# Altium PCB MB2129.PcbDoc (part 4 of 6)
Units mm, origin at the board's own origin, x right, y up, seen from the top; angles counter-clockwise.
Board outline 70 x 133.34 mm, 6 copper layers (Top Layer, Signal Layer 1, Signal Layer 2, Signal Layer 3, Signal Layer 4, Bottom Layer), stack 1.57 mm thick; 377 components, 289 nets, 1482 pads, 1373 vias.
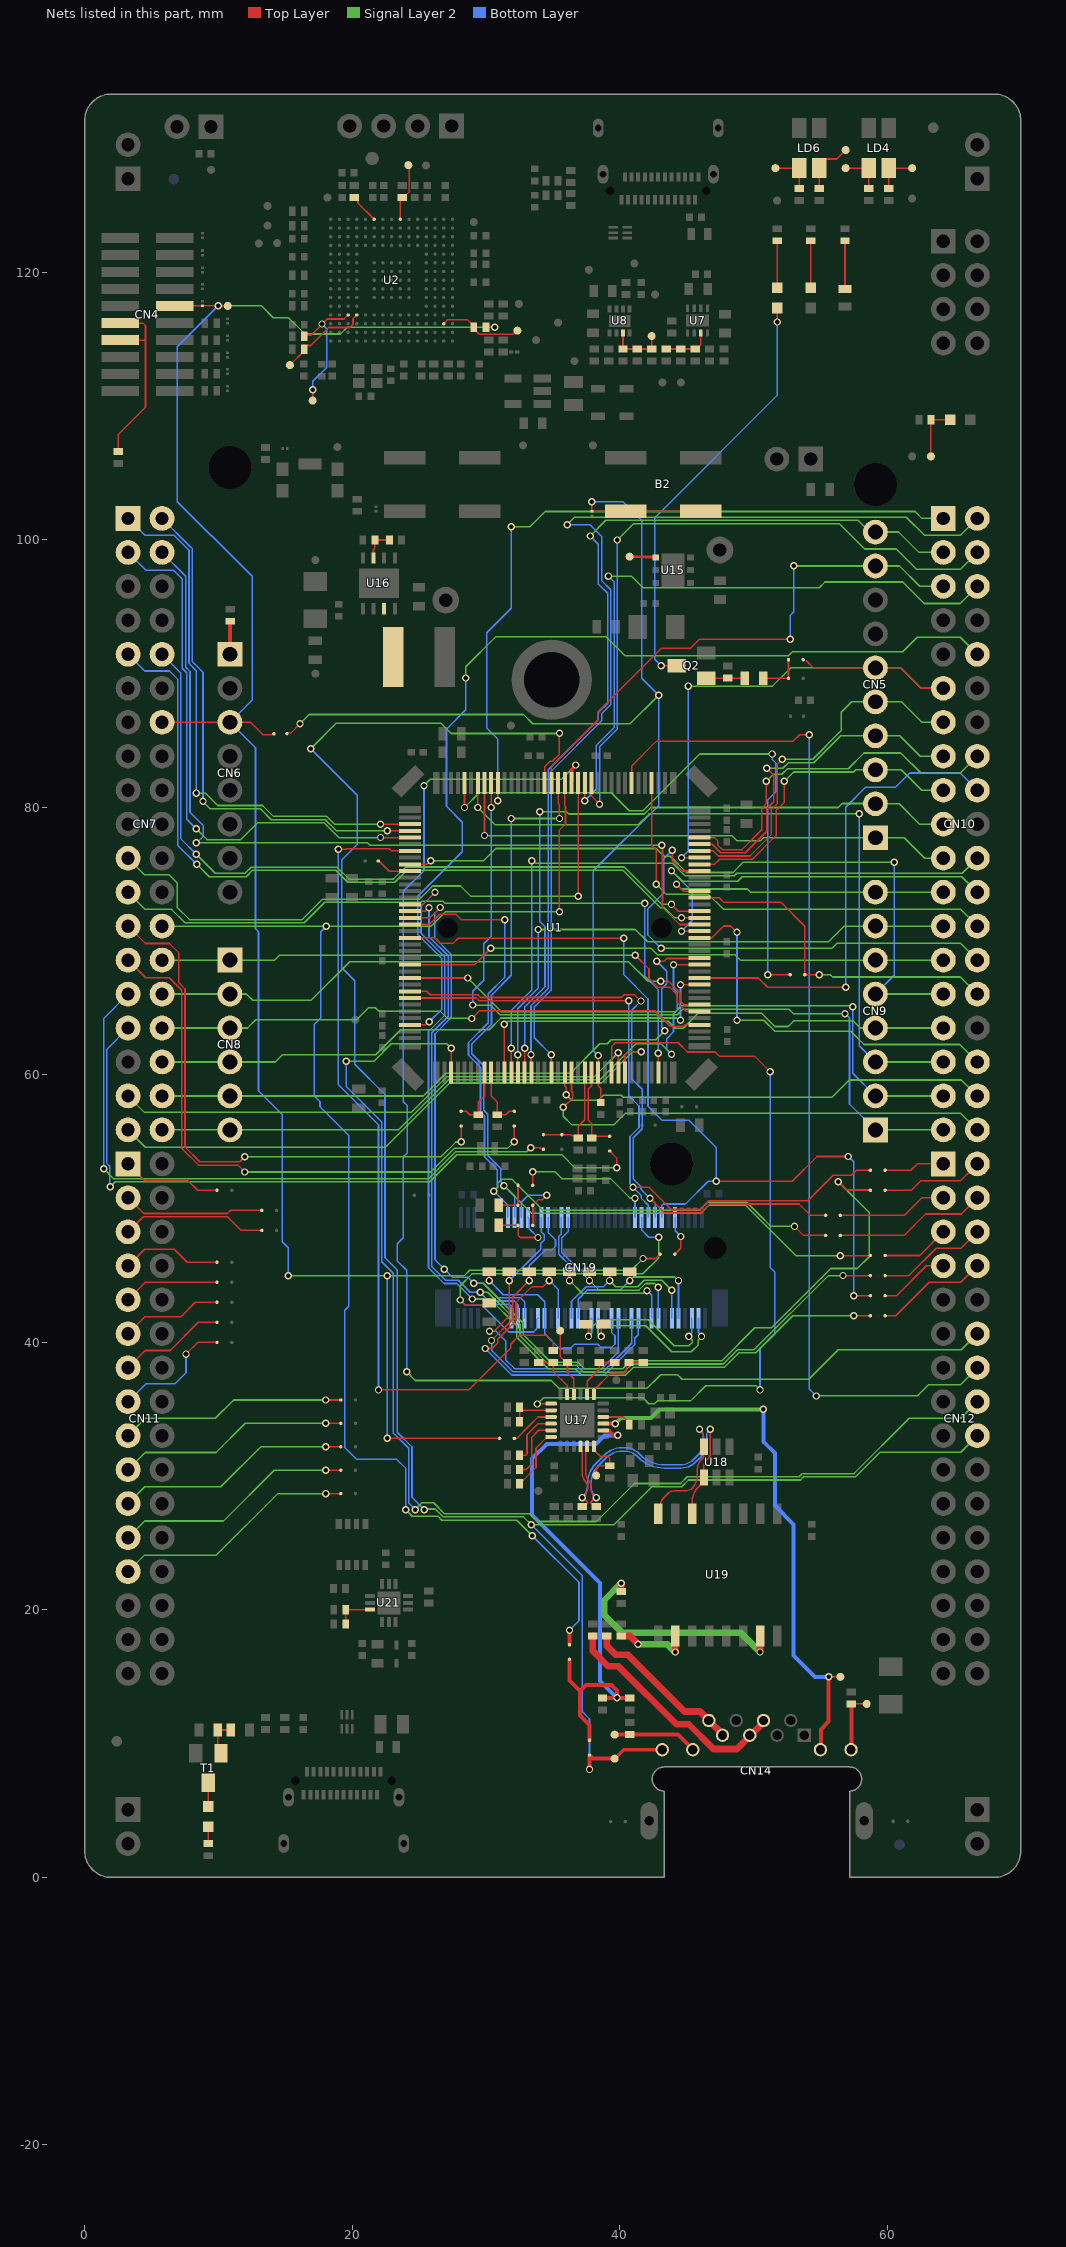
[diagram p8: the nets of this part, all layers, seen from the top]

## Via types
v1: diameter 0.55, hole 0.35, Top Layer to Bottom Layer, tented both sides, 1373 vias

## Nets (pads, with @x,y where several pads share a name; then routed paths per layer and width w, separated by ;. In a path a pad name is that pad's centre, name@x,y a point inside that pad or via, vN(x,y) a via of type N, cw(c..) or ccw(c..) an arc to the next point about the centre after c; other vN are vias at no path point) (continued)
NetCN4_11: CN4.11 CN4.13 R50.2 | length 14.1
  Top Layer w0.12: R50.2@2.5,106.625 2.5,107.871 4.55,109.921 4.55,114.929 ; CN4.13@2.665,114.945 4.534,114.945 4.55,114.929 ; CN4.11@2.665,116.215 4.36,116.215 4.55,116.025 4.55,114.929
NetCN6_1: CN6.1 R59.1 | length 2.5
  Top Layer w0.12: CN6.1@10.866,91.45 CN6.1@10.875,91.459
  Top Layer w0.3: CN6.1@10.875,91.459 R59.1@10.875,93.925
NetCN11_1: CN11.1 SB7.2 | length 7.5
  Top Layer w0.12: CN11.1@3.246,53.35 4.496,52.1 7.725,52.1 8.45,51.375 SB7.2@9.9,51.375
NetCN11_3: CN11.3 SB15.2 | length 10.6
  Top Layer w0.12: CN11.3@3.246,50.81 4.416,49.64 10.683,49.64 10.918,49.875 SB15.2@13.25,49.875
NetCN11_5: CN11.5 SB16.2 | length 10.9
  Top Layer w0.12: CN11.5@3.246,48.27 4.376,49.4 10.675,49.4 11.7,48.375 SB16.2@13.25,48.375
NetCN11_7: CN11.7 SB17.2 | length 7.6
  Top Layer w0.12: CN11.7@3.246,45.73 4.491,46.975 6.7,46.975 7.675,46 SB17.2@9.9,46
NetCN11_9: CN11.9 SB18.2 | length 7.2
  Top Layer w0.12: CN11.9@3.246,43.19 4.556,44.5 SB18.2@9.9,44.5
NetCN11_11: CN11.11 SB20.2 | length 7.6
  Top Layer w0.12: CN11.11@3.246,40.65 4.521,41.925 7.2,41.925 8.275,43 SB20.2@9.9,43
NetCN11_13: CN11.13 SB21.2 | length 8.1
  Top Layer w0.12: CN11.13@3.246,38.11 4.536,39.4 6.4,39.4 8.5,41.5 SB21.2@9.9,41.5
NetCN11_15: CN11.15 SB22.2 | length 9.3
  Top Layer w0.12: v1(7.579,39.13) 8.449,40 SB22.2@9.9,40
  Bottom Layer w0.12: CN11.15@3.246,35.57 4.576,36.9 6.734,36.9 7.579,37.744 v1(7.579,39.13)
NetCN11_17: CN11.17 SB23.2 | length 17
  Top Layer w0.12: v1(18.025,35.7) SB23.2@19.15,35.7
  Signal Layer 2 w0.12: CN11.17@3.246,33.03 4.541,34.325 9.775,34.325 11.15,35.7 v1(18.025,35.7)
NetCN11_19: CN11.19 SB24.2 | length 17.3
  Top Layer w0.12: v1(18.025,33.95) SB24.2@19.15,33.95
  Signal Layer 2 w0.12: CN11.19@3.246,30.49 4.531,31.775 9.825,31.775 12,33.95 v1(18.025,33.95)
NetCN11_21: CN11.21 SB28.2 | length 17.7
  Top Layer w0.12: v1(18.025,32.2) SB28.2@19.15,32.2
  Signal Layer 2 w0.12: CN11.21@3.246,27.95 4.496,29.2 10.186,29.2 13.186,32.2 v1(18.025,32.2)
NetCN11_23: CN11.23 SB26.2 | length 18
  Top Layer w0.12: v1(18.025,30.45) SB26.2@19.15,30.45
  Signal Layer 2 w0.12: CN11.23@3.246,25.41 4.486,26.65 10.375,26.65 14.175,30.45 v1(18.025,30.45)
NetCN11_25: CN11.25 SB27.2 | length 18.3
  Top Layer w0.12: v1(18.025,28.7) SB27.2@19.15,28.7
  Signal Layer 2 w0.12: CN11.25@3.246,22.87 4.476,24.1 9.85,24.1 14.45,28.7 v1(18.025,28.7)
NetCN12_1: CN12.1 SB29.2 | length 4.6
  Top Layer w0.12: SB29.2@59.85,52.875 61.775,52.875 62.25,53.35 CN12.1@64.206,53.35
NetCN12_2: CN12.2 SB31.2 | length 7.7
  Top Layer w0.12: SB31.2@59.85,51.375 61.825,51.375 62.525,52.075 65.471,52.075 CN12.2@66.746,53.35
NetCN12_3: CN12.3 SB30.2 | length 8.3
  Top Layer w0.12: SB30.2@56.5,49.5 61.3,49.5 62.61,50.81 CN12.3@64.206,50.81
  Signal Layer 2 w0.12: CN12.3@64.198,50.818 CN12.3@64.206,50.81
NetCN12_4: CN12.4 SB34.2 | length 11.4
  Top Layer w0.12: SB34.2@56.5,48 61.275,48 62.875,49.6 65.536,49.6 CN12.4@66.746,50.81
NetCN12_5: CN12.5 SB36.2 | length 5.1
  Top Layer w0.12: SB36.2@59.85,46.5 62.436,46.5 CN12.5@64.206,48.27
  Signal Layer 2 w0.12: CN12.5@64.203,48.273 CN12.5@64.206,48.27
NetCN12_6: CN12.6 SB33.2 | length 8.3
  Top Layer w0.12: SB33.2@59.85,45 61.625,45 63.675,47.05 65.526,47.05 CN12.6@66.746,48.27
NetCN12_7: CN12.7 SB37.2 | length 5.3
  Top Layer w0.12: SB37.2@59.85,43.5 60.697,43.5 62.927,45.73 CN12.7@64.206,45.73
  Signal Layer 2 w0.12: CN12.7@64.196,45.74 CN12.7@64.206,45.73
NetCN12_8: CN12.8 SB32.2 | length 8.4
  Top Layer w0.12: SB32.2@59.85,42 60.65,42 63.15,44.5 65.516,44.5 CN12.8@66.746,45.73
NetCN14_4: CN14.4 CN14.5 R92.2 | length 17.9
  Top Layer w0.5: R92.2@37.997,18.054 37.997,16.929 39.147,15.779 39.922,15.779 44.247,11.454 45.172,11.454 47.022,9.604 48.769,9.604 49.765,10.6 50.785,11.62 CN14.4@50.785,11.7
NetCN14_7: CN14.7 CN14.8 R93.2 | length 12.3
  Top Layer w0.5: R93.2@39.047,18.054 39.047,17.304 39.697,16.654 40.597,16.654 44.847,12.404 46.001,12.404 46.705,11.7 47.725,10.68 CN14.7@47.725,10.6
NetCN14_9: CN14.9 R95.2 TP69.1 | length 4.6
  Top Layer w0.12: R95.2@57.325,12.975 TP69.1@58.475,12.975
  Top Layer w0.3: R95.2@57.325,12.975 57.335,12.965 CN14.9@57.335,9.52
NetCN14_10: CN14.10 TP65.1 U17.3 | length 41.6
  Top Layer w0.12: v1(55.625,15) TP65.1@56.5,15
  Top Layer w0.3: U17.3@38.775,33.925 v1(39.675,33.925) ; CN14.10@55.045,9.52 55.045,11.064 55.625,11.644 v1(55.625,15)
  Signal Layer 2 w0.3: v1(39.675,33.925) 40.115,34.365 42.359,34.365 42.994,35 v1(50.75,35)
  Bottom Layer w0.3: v1(50.75,35) 50.75,32.575 51.6,31.725 51.6,27.8 53,26.4 53,16.6 54.15,15.45 54.6,15 v1(55.625,15)
NetCN14_11: CN14.11 R102.2 TP72.1 | length 6.3
  Top Layer w0.3: TP72.1@39.625,10.675 R102.2@40.75,10.675 44.35,10.675 CN14.11@45.475,9.55
NetCN19_20: CN19.20 SB11.1 SB12.1 | length 6.1
  Top Layer w0.12: SB11.1@33.5,48.75 SB12.1@33.5,50.25 33.933,50.683 34.263,50.683 34.55,50.97 v1(34.55,51)
  Bottom Layer w0.12: CN19.20@32.65,49.35 32.65,50.475 33.175,51 v1(34.55,51)
NetCN19_22: CN19.22 R67.2 SB11.2 | length 5.6
  Top Layer w0.12: R67.2@30.95,48.75 SB11.2@32.4,48.75 32.425,48.725 32.425,48 32.575,47.85 v1(33.9,47.85)
  Bottom Layer w0.12: CN19.22@33.15,49.35 33.24,49.26 33.24,48.51 v1(33.9,47.85)
NetCN19_25: CN19.25 CN19.56 R107.2 | length 30.8
  Top Layer w0.12: v1(28.075,43.175) 28.475,42.775 30.075,42.775 R107.2@30.25,42.95
  Signal Layer 2 w0.12: v1(28.075,43.175) 28.075,44.239 28.961,45.125 40.925,45.125 40.93,45.13 41.735,45.13 42.925,46.32 v1(42.925,47.875)
  Bottom Layer w0.12: v1(28.075,43.175) 28.475,42.775 29.713,42.775 31.708,40.78 33.56,40.78 33.81,41.03 33.81,41.71 CN19.25@33.9,41.8 ; CN19.56@41.65,49.35 41.65,48.411 42.186,47.875 v1(42.925,47.875)
NetCN19_26: CN19.26 CN19.49 R63.2 | length 26.3
  Top Layer w0.12: v1(30.275,40.825) 30.314,40.864 30.639,40.864 31.75,41.975 v1(31.75,44.625) R63.2@31.75,45.3 31.61,45.3 R63.2@31.35,45.04
  Bottom Layer w0.12: v1(30.275,40.825) 30.775,40.825 31.496,40.104 31.496,38.683 32.134,38.045 38.656,38.045 39.9,39.289 CN19.49@39.9,41.8 ; v1(31.75,44.625) 34.1,46.975 34.1,47.407 34.355,47.662 34.355,48.046 34.15,48.251 CN19.26@34.15,49.35
NetCN19_27: CN19.27 CN19.47 R66.2 | length 15.9
  Top Layer w0.12: v1(30.25,44.625) R66.2@30.25,45.3
  Bottom Layer w0.12: v1(30.25,44.625) 31.3,43.575 33.875,43.575 34.4,43.05 CN19.27@34.4,41.8 34.4,40.65 35.504,39.546 36.31,39.546 36.619,39.855 38.372,39.855 38.607,39.62 39.388,39.62 39.655,39.887 39.655,40.492 39.4,40.747 CN19.47@39.4,41.8
NetCN19_28: CN19.28 CN19.53 R58.2 | length 27
  Top Layer w0.12: v1(30.425,40.15) 32.004,41.729 32.004,43.379 v1(33.25,44.625) R58.2@33.25,45.3
  Bottom Layer w0.12: v1(30.425,40.15) 30.425,39.414 32.034,37.805 38.755,37.805 40.9,39.95 CN19.53@40.9,41.8 ; v1(33.25,44.625) 33.25,45.733 34.437,46.92 34.938,46.92 35.205,47.187 35.205,47.688 34.65,48.243 CN19.28@34.65,49.35
NetCN19_31: CN19.31 CN19.55 R57.2 | length 26.7
  Top Layer w0.12: v1(29.95,39.55) 30.468,39.55 30.88,39.962 30.88,40.248 32.25,41.618 32.25,42.982 33.443,44.175 34.3,44.175 v1(34.75,44.625) R57.2@34.75,45.3
  Bottom Layer w0.12: v1(29.95,39.55) 31.935,37.565 38.854,37.565 41.14,39.851 41.14,40.315 41.4,40.575 CN19.55@41.4,41.8 ; v1(34.75,44.625) 35.4,43.975 CN19.31@35.4,41.8
NetCN19_32: CN19.32 CN19.59 R56.2 | length 14.3
  Top Layer w0.12: v1(36.25,44.625) R56.2@36.25,45.3
  Signal Layer 2 w0.12: v1(36.25,44.625) 37.2,43.675 41.765,43.675 41.965,43.875 v1(42.05,43.875)
  Bottom Layer w0.12: CN19.32@35.65,49.35 35.65,48.133 35.445,47.928 35.445,46.6 36.25,45.795 v1(36.25,44.625) ; v1(42.05,43.875) 42.4,43.525 CN19.59@42.4,41.8
NetCN19_34: CN19.34 CN19.61 R53.2 | length 14.6
  Top Layer w0.12: v1(37.75,44.625) R53.2@37.75,45.3
  Signal Layer 2 w0.12: v1(37.75,44.625) 38.46,43.915 41.447,43.915 41.942,44.41 42.641,44.41 42.9,44.151 v1(42.9,44.125)
  Bottom Layer w0.12: CN19.34@36.15,49.35 36.15,48.294 35.685,47.829 35.685,46.699 37.75,44.634 v1(37.75,44.625) ; CN19.61@42.9,41.8 v1(42.9,44.125)
NetCN19_35: CN19.35 CN19.65 R52.2 | length 12.9
  Top Layer w0.12: v1(39.25,44.625) R52.2@39.25,45.3
  Signal Layer 2 w0.12: v1(39.25,44.625) 39.72,44.155 41.347,44.155 41.842,44.65 43.15,44.65 v1(43.9,43.9)
  Bottom Layer w0.12: CN19.35@36.4,41.8 36.4,43.075 37.495,44.17 38.795,44.17 v1(39.25,44.625) ; CN19.65@43.9,41.8 v1(43.9,43.9)
NetCN19_37: CN19.37 CN19.67 R51.2 | length 13.2
  Top Layer w0.12: v1(40.75,44.625) R51.2@40.75,45.3
  Signal Layer 2 w0.12: v1(40.75,44.625) 40.764,44.625 41.029,44.89 44.121,44.89 44.386,44.625 v1(44.4,44.625)
  Bottom Layer w0.12: CN19.37@36.9,41.8 36.9,43.236 37.589,43.925 40.05,43.925 v1(40.75,44.625) ; CN19.67@44.4,41.8 v1(44.4,44.625)
NetCN19_41: CN19.41 CN19.71 R108.2 | length 13.8
  Top Layer w0.12: R108.2@37.475,41.35 37.675,41.15 v1(37.675,40.45)
  Signal Layer 2 w0.12: v1(37.675,40.45) 37.675,40.468 37.925,40.718 37.925,41.111 38.514,41.7 42.136,41.7 44.086,39.75 45.175,39.75 45.425,40 45.425,40.182 45.175,40.432 v1(45.175,40.45)
  Bottom Layer w0.12: v1(37.675,40.45) 37.675,40.509 37.9,40.734 CN19.41@37.9,41.8 ; v1(45.175,40.45) 45.175,40.509 45.4,40.734 CN19.71@45.4,41.8
NetCN19_43: CN19.43 CN19.73 R109.2 | length 13.8
  Top Layer w0.12: v1(38.625,40.45) 38.625,41.15 R109.2@38.825,41.35
  Signal Layer 2 w0.12: v1(38.625,40.45) 38.625,40.468 38.375,40.718 38.375,40.925 38.7,41.25 41.95,41.25 43.9,39.3 45.361,39.3 45.875,39.814 45.875,40.182 46.125,40.432 v1(46.125,40.45)
  Bottom Layer w0.12: CN19.43@38.4,41.8 38.4,40.734 38.625,40.509 v1(38.625,40.45) ; CN19.73@45.9,41.8 45.9,40.734 46.125,40.509 v1(46.125,40.45)
NetCN19_54: CN19.54 SB39.1 | length 10.9
  Top Layer w0.12: SB39.1@33.5,51.75 v1(33.5,52.75)
  Signal Layer 2 w0.12: v1(33.5,52.75) 35.19,52.75 35.715,52.225 39.35,52.225 40.773,50.802 41.123,50.802 v1(41.15,50.775)
  Bottom Layer w0.12: CN19.54@41.15,49.35 v1(41.15,50.775)
NetCN19_66: CN19.66 SB25.1 | length 3.1
  Top Layer w0.12: SB25.1@44.125,46.6 44.575,47.05 v1(44.575,47.925)
  Bottom Layer w0.12: CN19.66@44.15,49.35 44.15,48.35 v1(44.575,47.925)
NetL2_1: L2.1 U16.7
NetLD1_1: LD1.1 R17.1 | length 3.5
  Top Layer w0.12: LD1.1@51.775,118.85 R17.1@51.775,122.375
NetLD1_2: LD1.2 Q2.3 | length 31.9
  Top Layer w0.12: v1(43.1,90.6) Q2.3@44.277,90.6 ; v1(51.775,116.3) LD1.2@51.775,117.35
  Bottom Layer w0.12: v1(43.1,90.6) 42.625,91.075 42.625,101.65 51.775,110.8 v1(51.775,116.3)
NetLD2_1: LD2.1 R18.1 | length 3.5
  Top Layer w0.12: LD2.1@54.3,118.85 R18.1@54.3,122.375
NetLD3_1: LD3.1 R19.1 | length 3.5
  Top Layer w0.12: LD3.1@56.85,118.85 R19.1@56.85,122.375
NetLD4_1: LD4.1 R12.1 TP7.1 | length 3.3
  Top Layer w0.12: R12.1@60.125,126.275 LD4.1@60.125,127.8 TP7.1@61.875,127.8
NetLD4_2: LD4.2 R11.2 TP6.1 | length 3.2
  Top Layer w0.12: TP6.1@56.9,127.8 LD4.2@58.625,127.8 R11.2@58.625,126.275
NetLD5_1: LD5.1 R105.1 | length 1.3
  Top Layer w0.12: R105.1@9.25,2.525 LD5.1@9.25,3.8
NetLD5_2: LD5.2 T1.3 | length 1.8
  Top Layer w0.12: LD5.2@9.25,5.3 T1.3@9.25,7.075
NetLD6_1: LD6.1 R10.1 TP1.1 | length 4.2
  Top Layer w0.12: R10.1@54.925,126.275 LD6.1@54.925,127.8 54.925,128 55.411,128.487 56.237,128.487 TP1.1@56.9,129.15
NetLD6_2: LD6.2 R9.1 TP5.1 | length 3.3
  Top Layer w0.12: TP5.1@51.65,127.8 LD6.2@53.425,127.8 R9.1@53.425,126.275
NetLD7_1: LD7.1 R48.1 TP39.1 | length 4.2
  Top Layer w0.12: TP39.1@63.275,106.25 R48.1@63.275,109 LD7.1@64.725,109
NetQ2_1: Q2.1 R111.2 R112.1 | length 2.9
  Top Layer w0.12: Q2.1@46.477,89.65 48.05,89.65 R112.1@48.075,89.675 R111.2@49.35,89.675
NetR7_1: R7.1 U2.F15 | length 2.3
  Top Layer w0.12: R7.1@20.15,125.6 20.245,125.6 20.44,125.405 20.44,125.185 U2.F15@21.65,123.975
NetR8_1: R8.1 TP3.1 U2.J15 | length 4.4
  Top Layer w0.12: U2.J15@23.6,123.975 23.6,125.6 R8.1@23.695,125.6 ; R8.1@23.75,125.6 23.845,125.6 24.26,126.015 24.26,127.965 TP3.1@24.2,128.025
NetR27_1: R27.1 TP27.1 U2.P3 | length 6.3
  Top Layer w0.12: U2.P3@26.85,116.175 27.155,116.48 28.615,116.48 29.1,115.995 R27.1@29.1,115.9 29.1,115.805 29.515,115.39 32.04,115.39 32.3,115.65 TP27.1@32.35,115.65
NetR28_1: R28.1 TP34.1 U2.C4 | length 10.2
  Top Layer w0.12: R28.1@16.425,115.325 16.937,115.325 18.137,116.525 19.4,116.525 U2.C4@19.7,116.825 ; TP34.1@17.05,110.425 17.055,110.43 17.055,111.219 v1(17.059,111.224)
  Bottom Layer w0.12: v1(17.059,111.224) 17.059,111.253 17.059,111.859 18.1,112.9 18.1,115.8 v1(17.75,116.15)
NetR32_1: R32.1 TP31.1 U2.D4 | length 6.9
  Top Layer w0.12: TP31.1@15.35,113.075 15.35,113.08 16.425,114.155 R32.1@16.425,114.25 16.425,114.345 16.62,114.54 16.91,114.54 18.26,115.89 19.818,115.89 20.065,116.137 20.065,116.54 U2.D4@20.35,116.825
NetR34_1: R34.1 R35.1 R36.1 TP28.1 U8.7 | length 4.3
  Top Layer w0.12: U8.7@40.25,115.475 R34.1@40.25,114.275 R35.1@41.325,114.275 R36.1@42.4,114.275 TP28.1@42.4,115.25
NetR37_1: R37.1 R38.1 R39.1 U7.7 | length 3.6
  Top Layer w0.12: R37.1@43.5,114.275 R38.1@44.575,114.275 R39.1@45.65,114.275 45.745,114.275 46.075,114.605 U7.7@46.075,115.475
NetR54_2: R54.2 R55.1 U16.3 | length 2.4
  Top Layer w0.12: U16.3@21.6,98.65 21.6,99.3 21.7,99.4 R54.2@21.7,100.025 ; R54.2@21.775,100 22.75,100 R55.1@22.775,99.975
NetR70_1: R70.1 R71.2 U17.11 | length 3.9
  Top Layer w0.12: R70.1@33.95,38.5 R71.2@35.025,38.5 35.025,37.825 36.075,36.775 U17.11@36.075,36.125
NetR72_1: R72.1 TP54.1 U17.10 | length 5.3
  Top Layer w0.12: TP54.1@35.552,40.878 TP54.1@35.555,40.875 ; TP54.1@35.61,40.93 TP54.1@35.555,40.875 ; U17.10@36.575,36.125 36.575,37.275 36.1,37.75 R72.1@36.1,38.5 36.005,38.5 35.555,38.95 TP54.1@35.555,40.875
NetR73_1: R73.1 R74.2 U17.8 | length 3.9
  Top Layer w0.12: U17.8@37.575,36.125 37.575,37.1 38.475,38 R73.1@38.475,38.5 R74.2@39.625,38.5
NetR75_2: R75.2 R76.1 U17.7 | length 5.2
  Top Layer w0.12: U17.7@38.075,36.125 38.075,36.433 39.317,37.675 40.3,37.675 40.503,37.878 40.503,38.303 R75.2@40.7,38.5 R76.1@41.821,38.5
NetR77_2: R77.2 R78.1 U17.14 | length 3.5
  Top Layer w0.12: R78.1@32.525,34.075 R77.2@32.525,35.15 32.75,34.925 U17.14@34.875,34.925
NetR79_2: R79.2 U17.4 | length 2.3
  Top Layer w0.12: U17.4@38.775,34.425 40.275,34.425 40.725,33.975 R79.2@40.725,33.85
NetR80_2: R80.2 U17.16 | length 4.2
  Top Layer w0.12: R80.2@32.525,31.575 32.975,31.575 33.075,31.675 33.075,33.1 33.9,33.925 U17.16@34.875,33.925
NetR81_1: R81.1 TP56.1 U17.24 | length 3.9
  Top Layer w0.12: U17.24@38.075,32.225 38.075,31.975 38.55,31.5 39.085,31.5 39.275,31.31 R81.1@39.275,30.775 38.5,30.775 38.25,30.525 TP56.1@38.25,30.05
NetR82_2: R82.2 U17.17 | length 4.7
  Top Layer w0.12: R82.2@32.525,30.5 33.025,30.5 33.425,30.9 33.425,32.9 33.95,33.425 U17.17@34.875,33.425
NetR83_2: R83.2 U17.18 | length 4.7
  Top Layer w0.12: R83.2@32.525,29.425 32.525,29.52 32.72,29.715 32.815,29.715 33.75,30.65 33.75,32.097 34.578,32.925 U17.18@34.875,32.925
NetR89_2: R89.2 U19.15 | length 17.5
  Top Layer w0.5: R89.2@40.125,21.375 v1(40.125,22) ; v1(50.5,16.85) U19.15@50.5,18.05
  Signal Layer 2 w0.5: v1(40.125,22) 38.85,20.725 38.85,19.625 40.173,18.302 49.048,18.302 v1(50.5,16.85)
NetR90_1: R90.1 R91.1 U21.6 | length 2.9
  Top Layer w0.12: R91.1@19.525,18.95 R90.1@19.525,20.025 U21.6@21.325,20.025
NetR94_2: R94.2 U19.10 | length 5.7
  Top Layer w0.5: R94.2@40.125,18.05 40.13,18.045 40.77,18.045 v1@41.365,17.45 ; v1(44.15,16.85) U19.10@44.15,18.05
  Signal Layer 2 w0.5: v1(41.375,17.44) 43.546,17.44 44.136,16.85 v1(44.15,16.85)
NetR96_2: R96.2 R98.1 SB13.1 SB38.1 U17.2 | length 41.2
  Top Layer w0.3: SB38.1@36.25,16.3 36.25,14.725 37.025,13.95 ; SB13.1@37.75,10.25 37.75,11.4 37.025,12.125 37.025,13.95 ; R98.1@38.725,13.425 39.794,13.425 v1(39.8,13.431) ; U17.2@38.775,33.425 39.188,33.425 39.515,33.098 39.802,33.098 v1(39.85,33.05) ; R96.2@40.748,13.423 40.741,13.429 v1(39.8,13.431) ; 37.025,13.95 37.475,14.4 39.375,14.4 39.8,13.975 v1(39.8,13.431) v1(39.8,13.431)
  Bottom Layer w0.3: v1(39.8,13.431) 38.55,14.681 38.55,22 33.466,27.084 33.466,31.308 34.558,32.4 38.225,32.4 38.875,33.05 v1(39.85,33.05)
NetR103_2: R103.2 R104.1 T1.1 | length 3.5
  Top Layer w0.12: T1.1@10.2,9.275 9.95,9.525 9.95,10.775 9.7,11.025 9.76,11.025 10.875,11.025 R104.1@10.925,11.025 ; R104.1@10.875,11.075 R104.1@10.925,11.025 ; R104.1@11.175,11.025 R104.1@10.925,11.025
NetR106_2: R106.2 SB12.2 SB39.2 | length 3
  Top Layer w0.12: R106.2@30.95,50.25 32.025,50.25 32.1,50.325 32.149,50.276 32.374,50.276 SB12.2@32.4,50.25 SB39.2@32.4,51.75
NetR111_1: R111.1 SB8.2 SB9.2 | length 3.3
  Top Layer w0.12: R111.1@50.75,89.675 52.6,89.675 SB8.2@52.625,89.65 SB9.2@52.625,91.05
NetSB35_2: SB35.2 U17.15 | length 3.4
  Top Layer w0.12: SB35.2@32.125,32.825 32.3,32.825 33.325,33.85 33.9,34.425 U17.15@34.875,34.425
NetTP43_1: TP43.1 U15.4 | length 2
  Top Layer w0.2: TP43.1@40.75,98.75 41.9,98.75 41.925,98.725 42.675,98.725 U15.4@42.7,98.7
NRST: CN4.10 CN6.3 CN7.14 R27.2 SB25.2 SB35.1 SB46.2 TP25.1 U6.1 | length 162.9
  Top Layer w0.12: CN7.14@5.786,86.37 CN6.3@10.866,86.37 12.405,86.37 13.35,85.425 14.265,85.425 ; CN4.10@6.735,117.485 6.757,117.506 U6.1@8.8,117.506 8.803,117.503 v1(9.991,117.503) 10.697,117.503 TP25.1@10.7,117.5 ; v1(22.625,32.825) SB35.1@31.025,32.825 ; R27.2@30,115.9 v1(30.675,115.9) ; v1(41.75,46.275) 41.755,46.28 42.705,46.28 SB25.2@43.025,46.6
  Signal Layer 2 w0.12: v1(9.991,117.503) 13.226,117.503 14.104,116.625 15.25,116.625 16.475,115.4 19.125,115.4 19.625,115.9 v1(30.675,115.9) ; v1(15.225,44.975) v1(22.625,44.975) 28.364,44.975 28.789,45.4 40.875,45.4 v1(41.75,46.275)
  Bottom Layer w0.12: v1(9.991,117.503) 6.925,114.437 6.925,102.864 9.465,100.324 9.494,100.324 12.525,97.293 12.525,88.029 CN6.3@10.866,86.37 12.775,84.461 12.775,70.925 13,70.7 13,58.825 14.775,57.05 14.775,47.525 15.225,47.075 v1(15.225,44.975) ; v1(22.625,32.825) v1(22.625,44.975)
OSC32_IN: R1.2 SB1.1 U1.8 | length 4.7
  Top Layer w0.12: SB1.1@28.15,57.28 28.536,57.28 28.786,57.03 R1.2@29.425,57.03 29.425,57.8 29.425,57.95 29.9,58.425 U1.8@29.9,60.175
OSC32_OUT: R2.2 SB2.1 U1.9 | length 4.7
  Top Layer w0.12: U1.9@30.4,60.175 30.4,58.425 30.85,57.975 R2.2@30.85,57.03 31.489,57.03 31.739,57.28 SB2.1@32.125,57.28
OSC_IN: R3.1 SB3.1 SB5.1 U1.23 | length 7.8
  Top Layer w0.12: SB3.1@34.306,55.539 SB5.1@35.681,55.539 36.361,55.539 36.45,55.45 36.745,55.45 R3.1@36.906,55.289 36.906,56.156 37.4,56.65 U1.23@37.4,60.175
OSC_OUT: R4.1 SB4.1 U1.24 | length 6.5
  Top Layer w0.12: 37.9,56.375 37.65,56.625 37.65,58.944 37.906,59.2 U1.24@37.906,60.169 ; 37.906,56.375 R4.1@37.906,55.289 38.031,55.414 SB4.1@39.256,55.414
PA0: CN7.23 U1.34 | length 53.4
  Top Layer w0.12: U1.34@42.9,60.175 v1(42.9,61.625)
  Signal Layer 2 w0.12: CN7.23@3.246,73.67 4.541,72.375 6.5,72.375 7.5,71.375 16.425,71.375 17.96,72.91 25.149,72.91 25.219,72.98 26.788,72.98 26.943,72.825 v1(41.875,72.825)
  Bottom Layer w0.12: v1(41.875,72.825) 41.875,67.375 42.9,66.35 v1(42.9,61.625)
PA4: CN7.32 CN8.3 U1.40 | length 41.9
  Top Layer w0.12: v1(28.95,64.225) 29.525,64.8 42.625,64.8 43.78,63.645 44.788,63.645 44.893,63.75 U1.40@45.975,63.75
  Signal Layer 2 w0.12: CN7.32@5.786,63.51 CN8.3@10.866,63.51 12.185,63.51 12.8,64.125 20.325,64.125 21.23,65.03 21.738,65.03 22.018,64.75 26.6,64.75 27.125,64.225 v1(28.95,64.225)
PA6: CN7.28 CN8.1 U1.42 | length 42.8
  Top Layer w0.12: v1(41.175,68.95) 42.195,67.93 42.195,67.237 42.887,66.545 43.766,66.545 44.305,66.006 44.305,65.42 44.975,64.75 U1.42@45.975,64.75
  Signal Layer 2 w0.12: CN7.28@5.786,68.59 CN8.1@10.866,68.59 14.211,68.59 14.571,68.95 v1(41.175,68.95)
PA7: CN7.30 CN8.2 U1.43 | length 43.3
  Top Layer w0.12: v1(43.075,67) 43.65,67 44.545,66.105 44.545,65.519 44.814,65.25 U1.43@45.975,65.25
  Signal Layer 2 w0.12: CN7.30@5.786,66.05 CN8.2@10.866,66.05 12.085,66.05 12.56,65.575 16.925,65.575 19.82,68.47 40.672,68.47 42.145,66.997 v1@43.072,66.997
PA8: CN9.1 CN10.37 U1.100 | length 60.3
  Top Layer w0.12: v1(30.4,80) U1.100@30.4,81.825
  Signal Layer 2 w0.12: v1(29.025,65.225) 30.336,65.225 31.061,64.5 44.307,64.5 44.732,64.925 52.652,64.925 53.002,64.575 v1(56.85,64.575) ; CN9.1@59.126,55.89 CN10.37@64.206,55.89
  Bottom Layer w0.12: v1(29.025,65.225) 29.025,66.253 29.85,67.078 29.85,69.806 30.4,70.356 v1(30.4,80) ; v1(56.85,64.575) 56.884,64.575 57.185,64.274 57.185,57.831 CN9.1@59.126,55.89
PA9: CN5.1 CN10.21 U1.101 | length 39.1
  Top Layer w0.12: v1(29.9,77.898) U1.101@29.9,81.825
  Signal Layer 2 w0.12: v1(29.9,77.898) 48.377,77.898 48.75,77.525 50.55,77.525 50.75,77.725 ; 50.75,77.734 CN5.1@59.126,77.734 61.291,77.734 62.815,76.21 CN10.21@64.206,76.21
PA10: CN9.3 CN10.33 U1.102 | length 55.3
  Top Layer w0.12: v1(29.4,80) U1.102@29.4,81.825
  Signal Layer 2 w0.12: v1(29.4,80) 30.685,78.715 41.394,78.715 42.197,79.518 v1(57.921,79.518) ; CN9.3@59.126,60.97 CN10.33@64.206,60.97
  Bottom Layer w0.12: v1(57.921,79.518) 57.921,62.175 CN9.3@59.126,60.97
PA12: SB6.1 U1.104 | length 46.2
  Top Layer w0.12: v1(28.4,80) U1.104@28.4,81.825 ; v1(51.075,67.5) SB6.1@52.75,67.5
  Signal Layer 2 w0.12: v1(28.4,80) 29.5,81.1 39.375,81.1 40.725,79.75 41.75,79.75 46,84 v1(51.4,84)
  Bottom Layer w0.12: v1(51.075,67.5) 51.075,80.561 51.695,81.181 51.695,83.319 51.399,83.615 v1@51.399,83.999
PB0: CN7.34 CN8.4 U1.46 | length 44.3
  Top Layer w0.12: v1(44.55,66.75) U1.46@45.975,66.75
  Signal Layer 2 w0.12: CN7.34@5.786,60.97 CN8.4@10.866,60.97 14.252,60.97 14.787,61.505 15.163,61.505 21.776,61.505 23.646,63.375 30.25,63.375 31.135,64.26 44.274,64.26 44.434,64.1 v1(44.55,64.1)
  Bottom Layer w0.12: v1(44.55,64.1) v1(44.55,66.75)
PB1: CN10.18 U1.47 | length 35.4
  Top Layer w0.12: U1.47@46.65,67.25 50.375,67.25 51.075,66.55 v1(56.9,66.55)
  Bottom Layer w0.12: v1(56.9,66.55) 56.9,80.022 58.403,81.525 60.65,81.525 61.7,82.575 65.461,82.575 CN10.18@66.746,81.29
PB4: CN9.2 CN10.35 U1.134 | length 46.8
  Top Layer w0.12: U1.134@24.325,67.25 27.615,67.25 v1(28.65,67.25)
  Signal Layer 2 w0.12: v1(28.65,67.25) 31.16,64.74 44.19,64.74 44.615,65.165 57.36,65.165 v1(57.425,65.1) ; CN9.2@59.126,58.43 CN10.35@64.206,58.43
  Bottom Layer w0.12: v1(57.425,65.1) 57.425,60.131 CN9.2@59.126,58.43
PB6: CN19.60 SB30.1 U1.136 | length 49.7
  Top Layer w0.12: U1.136@24.325,66.25 25.581,66.25 25.841,65.99 29.394,65.99 29.594,65.79 40.132,65.79 40.347,66.005 41.12,66.005 v1(41.6,65.525) ; v1(42.275,50.775) 43.35,49.7 46.1,49.7 46.755,50.355 53.42,50.355 54.275,49.5 SB30.1@55.4,49.5
  Bottom Layer w0.12: v1(41.6,65.525) 40.915,64.84 40.915,59.703 41.655,58.964 41.69,58.928 41.69,55.976 41.02,55.306 41.02,52.223 41.598,51.646 41.598,51.452 v1(42.275,50.775) 42.65,50.4 CN19.60@42.65,49.35
PB7: CN19.58 SB29.1 U1.137 | length 53.5
  Top Layer w0.12: U1.137@24.325,65.75 29.295,65.75 29.495,65.55 v1(40.675,65.55) ; v1(41,51.6) 42.2,51.6 43.86,49.94 46.001,49.94 46.656,50.595 54.07,50.595 55.975,52.5 57.343,52.5 57.718,52.875 SB29.1@58.75,52.875
  Bottom Layer w0.12: v1(40.675,65.55) 40.675,58.45 41.415,57.71 41.45,57.675 41.45,56.075 40.78,55.405 40.78,51.885 41,51.665 v1(41,51.6) 41.605,50.995 41.605,50.795 42.15,50.25 CN19.58@42.15,49.35
PB15: CN10.26 U1.76 | length 33
  Top Layer w0.12: U1.76@42.4,81.825 42.4,77.15 42.75,76.8 v1(42.75,74.25)
  Signal Layer 2 w0.12: v1(42.75,74.25) 43.5,73.5 46.65,73.5 47.75,72.4 65.476,72.4 CN10.26@66.746,71.13
PC2: CN7.35 U1.28 | length 40.5
  Top Layer w0.12: U1.28@39.9,60.175 v1(39.9,61.65)
  Signal Layer 2 w0.12: CN7.35@3.246,58.43 4.476,57.2 24.421,57.2 27.101,59.88 38.13,59.88 v1(39.9,61.65)
PC3: CN7.37 U1.29 | length 44.5
  Top Layer w0.12: U1.29@40.4,60.175 40.4,61.5 40.625,61.725 40.725,61.725 v1(41.625,61.725)
  Signal Layer 2 w0.12: CN7.37@3.246,55.89 4.536,54.6 22.5,54.6 27.3,59.4 38.639,59.4 40.964,61.725 v1(41.625,61.725)
PC9: CN10.1 U1.99 | length 55.9
  Top Layer w0.12: v1(30.9,80.5) U1.99@30.9,81.825
  Signal Layer 2 w0.12: v1(31.9,101) 33.325,101 34.45,102.125 36.182,102.125 62.1,102.125 62.615,101.61 CN10.1@64.206,101.61
  Bottom Layer w0.12: v1(30.9,80.5) 30.9,85.096 30.06,85.936 30.06,93.064 31.9,94.904 v1(31.9,101)
PC10: CN7.1 U1.111 | length 40.9
  Top Layer w0.12: v1(22.125,78.75) U1.111@24.325,78.75
  Signal Layer 2 w0.12: v1(8.35,81.075) 9.025,81.075 9.95,80.15 13.3,80.15 14.12,79.33 18.099,79.33 18.679,78.75 v1(22.125,78.75)
  Bottom Layer w0.12: CN7.1@3.246,101.61 4.506,100.35 6.675,100.35 7.8,99.225 7.8,90.775 8.35,90.225 v1(8.35,81.075)
PC11: CN7.2 U1.112 | length 38.8
  Top Layer w0.12: v1(22.625,78.25) U1.112@24.325,78.25
  Signal Layer 2 w0.12: v1(8.85,80.475) 8.85,80.425 9.375,79.9 13.15,79.9 13.96,79.09 17.999,79.09 18.839,78.25 v1(22.625,78.25)
  Bottom Layer w0.12: CN7.2@5.786,101.61 7.825,99.571 8.04,99.356 8.04,90.91 8.85,90.1 v1(8.85,80.475)
PC12: CN7.3 U1.113 | length 41.3
  Top Layer w0.12: v1(22.125,77.75) U1.113@24.325,77.75
  Signal Layer 2 w0.12: v1(8.35,78.4) 9.15,77.6 11.675,77.6 12.925,78.85 17.9,78.85 19,77.75 v1(22.125,77.75)
  Bottom Layer w0.12: CN7.3@3.246,99.07 4.566,97.75 6.625,97.75 7.3,97.075 7.3,90.403 7.635,90.068 7.635,79.115 v1(8.35,78.4)
PC14: CN7.25 SB1.2 | length 42.2
  Top Layer w0.12: CN7.25@3.246,71.13 4.55,69.826 6.349,69.826 7.05,69.125 7.05,66.889 7.506,66.433 7.506,54.608 8.614,53.5 11.6,53.5 v1(11.975,53.875) ; v1(28.15,55.005) SB1.2@28.15,56.18
  Signal Layer 2 w0.12: v1(11.975,53.875) 26.65,53.875 27.765,54.99 28.135,54.99 v1(28.15,55.005)
PC15: CN7.27 SB2.2 | length 44.5
  Top Layer w0.12: CN7.27@3.246,68.59 4.561,67.275 6.325,67.275 7.266,66.334 7.266,54.509 8.515,53.26 11.465,53.26 v1(11.98,52.745) ; v1(32.125,55.005) SB2.2@32.125,56.18
  Signal Layer 2 w0.12: v1(11.98,52.745) 25.87,52.745 27.63,54.505 31.625,54.505 v1(32.125,55.005)
PD3: CN9.5 CN10.29 U1.117 | length 53.3
  Top Layer w0.12: U1.117@24.325,75.75 25.6,75.75 v1(25.875,76.025)
  Signal Layer 2 w0.12: v1(25.875,76.025) 29.825,76.025 30.735,76.935 42.747,76.935 43.337,76.345 43.788,76.345 44.993,75.14 48.476,75.14 49.251,75.915 v1(60.525,75.915) ; CN9.5@59.126,66.05 CN10.29@64.206,66.05
  Bottom Layer w0.12: CN9.5@59.126,66.05 60.525,67.449 v1(60.525,75.915)
PD4: SB14.1 U1.118 | length 2.7
  Top Layer w0.12: SB14.1@22,76 22,75.986 22.053,75.933 22.067,75.933 22.775,75.225 U1.118@24.325,75.225
PD7: CN19.17 SB32.1 U1.123 | length 74.8
  Top Layer w0.12: U1.123@24.325,72.75 25.3,72.75 v1(26.2,73.65) ; v1(57.5,42) SB32.1@58.75,42
  Signal Layer 2 w0.12: v1(28.975,43.25) 30.303,43.25 32.312,41.241 32.312,40.391 34.663,38.04 36.678,38.04 37.173,37.545 40.43,37.545 41.035,38.15 47.85,38.15 48.925,39.225 50.175,39.225 52.95,42 v1(57.5,42)
  Bottom Layer w0.12: v1(26.2,73.65) 25.15,72.6 25.15,70.596 26.94,68.806 26.94,64.487 25.71,63.257 25.71,45.576 26.877,44.409 27.816,44.409 v1(28.975,43.25) 29.7,43.25 30.095,42.855 31.745,42.855 31.9,42.7 CN19.17@31.9,41.8
PD10: CN12.14 U1.79 | length 78.1
  Top Layer w0.12: U1.79@40.9,81.825 40.9,83.1 42.765,84.965 52.99,84.965 53.465,85.44 v1(54.19,85.44)
  Signal Layer 2 w0.12: v1(54.7,36) 62.25,36 63.075,36.825 65.461,36.825 CN12.14@66.746,38.11
  Bottom Layer w0.12: v1(54.19,85.44) 54.19,36.51 v1(54.7,36)
PD14: CN10.4 U1.85 | length 51.5
  Top Layer w0.12: U1.85@37.9,81.825 37.9,80.85 v1(38.5,80.25)
  Signal Layer 2 w0.12: v1@39.827,100 41.027,101.2 56.45,101.2 58.325,99.325 60.675,99.325 62.175,97.825 65.501,97.825 CN10.4@66.746,99.07
  Bottom Layer w0.12: v1(38.5,80.25) 38.5,84.537 39.825,85.862 v1(39.825,99.998) v1@39.827,100
PD15: CN10.6 U1.86 | length 48.5
  Top Layer w0.12: v1(37.4,80.5) U1.86@37.4,81.825
  Signal Layer 2 w0.12: v1(39.162,97.3) 40.875,97.3 41.75,96.425 54.925,96.425 55.36,96.86 61.165,96.86 62.775,95.25 65.466,95.25 CN10.6@66.746,96.53
  Bottom Layer w0.12: v1(37.4,80.5) 38.26,81.36 38.26,84.636 39.585,85.961 39.585,96.877 v1(39.162,97.3)
PE0: CN10.10 U1.141 | length 72.5
  Top Layer w0.12: U1.141@24.325,63.75 25.49,63.75 25.715,63.975 v1(25.775,63.975)
  Signal Layer 2 w0.12: v1(28.5,89.675) 28.5,90.525 30.725,92.75 39,92.75 40.4,91.35 52.625,91.35 52.925,91.65 61.175,91.65 62.25,92.725 65.471,92.725 CN10.10@66.746,91.45
  Bottom Layer w0.12: v1(25.775,63.975) 26.7,64.9 26.7,68.707 24.91,70.497 24.91,73.371 28.235,76.696 28.235,78.901 27.055,80.081 27.055,85.851 28.5,87.296 v1(28.5,89.675)
PE4: CN12.16 U1.3 | length 92.5
  Top Layer w0.12: U1.3@27.4,60.175 v1(27.4,62)
  Signal Layer 2 w0.12: v1(19.55,61.025) 21.635,61.025 22.935,62.325 27.075,62.325 v1(27.4,62) ; v1(24.725,27.5) 25.23,28.005 26.095,28.005 26.905,27.195 33.28,27.195 33.865,26.61 38.267,26.61 41.112,29.455 44.551,29.455 45.051,29.955 53.422,29.955 53.662,30.195 57.531,30.195 61.661,34.325 65.501,34.325 CN12.16@66.746,35.57
  Bottom Layer w0.12: v1(19.55,61.025) 19.55,59.15 22.215,56.485 22.215,46.028 23.08,45.163 23.08,33.235 24.235,32.08 24.235,27.99 v1(24.725,27.5)
PE8: CN10.30 SB6.2 U1.59 | length 25.9
  Top Layer w0.12: U1.59@45.975,73.25 47.45,73.25 47.8,72.9 52.075,72.9 53.85,71.125 SB6.2@53.85,67.5 v1(54.925,67.5)
  Signal Layer 2 w0.12: v1(54.925,67.5) 55.75,67.5 55.925,67.325 65.471,67.325 CN10.30@66.746,66.05
PE9: CN9.8 CN10.23 U1.60 | length 22.1
  Top Layer w0.12: v1(44.25,74.25) 44.75,73.75 U1.60@45.975,73.75
  Signal Layer 2 w0.12: v1(44.25,74.25) 44.6,73.9 49.55,73.9 49.78,73.67 CN9.8@59.126,73.67 CN10.23@64.206,73.67
PE10: CN10.28 U1.63 | length 36
  Top Layer w0.12: v1(43.925,76.8) 43.925,76 44.675,75.25 U1.63@45.975,75.25
  Signal Layer 2 w0.12: v1(43.1,69.475) 55.875,69.475 56.25,69.85 65.486,69.85 CN10.28@66.746,68.59
  Bottom Layer w0.12: v1(43.1,69.475) 42.115,70.46 42.115,72.422 43.3,73.607 43.3,76.175 v1(43.925,76.8)
PE11: CN5.3 CN10.17 U1.64 | length 23.8
  Top Layer w0.12: U1.64@45.975,75.75 47.1,75.75 47.48,76.13 49.93,76.13 51.7,77.9 51.7,79.775 52.3,80.375 v1(52.3,81.95)
  Signal Layer 2 w0.12: v1@52.325,81.95 53.025,82.65 57.5,82.65 57.664,82.814 CN5.3@59.126,82.814 61.061,82.814 62.585,81.29 CN10.17@64.206,81.29
PE12: CN5.6 CN10.11 SB9.1 U1.65 | length 45.8
  Top Layer w0.12: v1(44.625,76.25) U1.65@45.975,76.25 ; 53.96,90.975 54.501,90.434 CN5.6@59.126,90.434 61.016,90.434 62.54,88.91 CN10.11@64.206,88.91
  Signal Layer 2 w0.12: v1(45.125,89.075) 51.438,89.075 52.797,90.434 CN5.6@59.126,90.434 61.016,90.434 62.54,88.91 CN10.11@64.206,88.91
  Bottom Layer w0.12: v1(44.625,76.25) 45.125,76.75 v1(45.125,89.075)
PE13: CN5.5 CN10.13 U1.66 | length 27.4
  Top Layer w0.12: U1.66@45.975,76.75 47,76.75 47.38,76.37 49.745,76.37 51.35,77.975 51.35,79.85 51.8,80.3 51.8,83.25 v1(52.162,83.612)
  Signal Layer 2 w0.12: v1(52.162,83.612) 54.437,83.612 56.575,85.75 56.575,87.118 57.351,87.894 CN5.5@59.126,87.894 61.081,87.894 62.605,86.37 CN10.13@64.206,86.37
PE14: CN5.4 CN10.15 U1.67 | length 25.9
  Top Layer w0.12: U1.67@45.975,77.25 46.925,77.25 47.565,76.61 49.385,76.61 51,78.225 51,79.9 51.525,80.425 51.525,82.4 v1(51,82.925)
  Signal Layer 2 w0.12: v1(51,82.925) 52.2,82.925 52.625,83.35 54.525,83.35 56.54,85.365 59.116,85.365 CN5.4@59.126,85.354 60.946,85.354 62.47,83.83 CN10.15@64.206,83.83
PE15: CN10.16 U1.68 | length 27.4
  Top Layer w0.12: U1.68@45.975,77.75 47.1,77.75 47.325,77.525 47.325,77.189 47.664,76.85 49.15,76.85 50.625,78.325 50.625,79.95 50.975,80.3 v1(50.975,81.95)
  Signal Layer 2 w0.12: v1(50.975,81.95) 51.5,82.475 52.125,82.475 52.55,82.9 57.1,82.9 58.275,84.075 61.025,84.075 62.55,82.55 65.45,82.55 CN10.16@66.725,83.825 ; CN10.16@66.738,83.838 CN10.16@66.746,83.83
PF1: CN9.4 CN10.31 U1.11 | length 38.1
  Top Layer w0.12: v1(31.375,63.8) 31.388,63.787 31.388,60.187 U1.11@31.4,60.175
  Signal Layer 2 w0.12: v1(31.375,63.8) 31.44,63.8 31.66,64.02 43.639,64.02 44.159,63.5 44.75,63.5 45.875,64.625 50.6,64.625 51.605,63.62 52.613,63.62 53.043,64.05 57.456,64.05 57.996,63.51 58.793,63.51 CN9.4@59.126,63.51 CN10.31@64.206,63.51
PF2: CN10.22 U1.12 | length 50.8
  Top Layer w0.12: U1.12@31.9,60.175 v1(31.9,62)
  Signal Layer 2 w0.12: v1(33.425,76.025) 33.51,76.025 33.71,75.825 43.968,75.825 44.893,74.9 48.575,74.9 48.75,75.075 65.611,75.075 CN10.22@66.746,76.21
  Bottom Layer w0.12: v1(31.9,62) 31.9,64.821 33.425,66.346 v1(33.425,76.025)
PF3: CN9.7 CN10.25 U1.13 | length 43
  Top Layer w0.12: v1(32.375,61.5) 32.375,60.2 U1.13@32.4,60.175
  Signal Layer 2 w0.12: v1(33.925,70.875) 41.175,70.875 42.1,69.95 ; 42.625,69.95 42.1,69.95 ; CN10.25@64.206,71.13 CN9.7@59.126,71.13 56.805,71.13 55.625,69.95 42.1,69.95
  Bottom Layer w0.12: v1(32.375,61.5) 32.375,64.95 33.925,66.5 v1(33.925,70.875)
PF4: CN5.2 CN10.19 U1.14 | length 51.5
  Top Layer w0.12: U1.14@32.9,60.175 v1(32.9,62)
  Signal Layer 2 w0.12: v1(34.025,79.675) 36.025,79.675 36.19,79.51 41.849,79.51 42.339,80 56.35,80 56.65,80.3 59.125,80.3 CN5.2@59.15,80.275 ; CN5.2@59.15,80.274 60.901,80.274 62.425,78.75 CN10.19@64.206,78.75
  Bottom Layer w0.12: v1(32.9,62) 32.9,65.075 34.42,66.595 34.42,71.08 34.025,71.475 v1(34.025,79.675)
PF5: CN5.10 CN10.3 U1.15 | length 70.9
  Top Layer w0.12: v1(33.375,61.5) 33.375,60.2 U1.15@33.4,60.175
  Signal Layer 2 w0.12: v1(37.8,100.3) 38.968,101.468 57.822,101.468 58.697,100.594 CN5.10@59.126,100.594 60.856,100.594 62.38,99.07 CN10.3@64.206,99.07
  Bottom Layer w0.12: v1(33.375,61.5) 33.375,65.175 34.66,66.46 34.66,82.824 38.41,86.574 38.41,87.103 39.105,87.798 39.105,96.02 38.41,96.715 38.41,99.69 v1(37.8,100.3)
PF6: CN10.2 U1.18 | length 78.2
  Top Layer w0.12: U1.18@34.9,60.175 v1(34.9,61.5)
  Signal Layer 2 w0.12: v1(36.075,101.15) 36.633,101.708 61.442,101.708 62.8,100.35 65.486,100.35 CN10.2@66.746,101.61
  Bottom Layer w0.12: v1(34.9,61.5) 33.625,62.775 33.625,65.086 34.9,66.361 34.9,82.725 38.65,86.475 38.65,87.003 39.345,87.698 39.345,96.28 38.65,96.975 38.65,100.275 37.775,101.15 v1(36.075,101.15)
PF8: CN10.36 U1.20 | length 33.9
  Top Layer w0.12: U1.20@35.9,60.175 35.9,59.162 35.998,59.063 v1(35.998,58.527)
  Signal Layer 2 w0.12: v1(35.998,58.527) 36.425,58.1 38.425,58.1 38.8,58.475 40.125,58.475 40.275,58.325 55.875,58.325 57.175,59.625 65.551,59.625 CN10.36@66.746,58.43
PF9: CN10.38 U1.21 | length 35.7
  Top Layer w0.12: v1@35.775,57.575 v1(35.792,57.575) 36.501,58.284 36.501,58.671 36.4,58.772 U1.21@36.4,60.175
  Signal Layer 2 w0.12: v1(35.792,57.575) 35.792,56.917 36.445,56.264 39.564,56.264 40.425,57.125 42.375,57.125 65.511,57.125 CN10.38@66.746,55.89
PF11: CN7.38 CN8.6 U1.49 | length 50.3
  Top Layer w0.12: v1(44.025,68.25) U1.49@45.975,68.25
  Signal Layer 2 w0.12: CN7.38@5.786,55.89 CN8.6@10.866,55.89 23.451,55.89 27.201,59.64 38.54,59.64 41.25,62.35 43.075,62.35 v1(43.875,61.55)
  Bottom Layer w0.12: v1(43.875,61.55) 43.515,61.91 43.515,62.714 44.025,63.224 44.025,64.575 44.31,64.86 44.31,66.163 44.025,66.448 v1(44.025,68.25)
PF12: CN7.36 CN8.5 U1.50 | length 48.7
  Top Layer w0.12: v1(42.775,68.5) 43.325,68.5 43.53,68.705 45.93,68.705 U1.50@45.975,68.75
  Signal Layer 2 w0.12: CN7.36@5.786,58.43 CN8.5@10.866,58.43 25.312,58.43 27.002,60.12 36.32,60.12 38.525,62.325 39.075,62.325 39.375,62.625 42.7,62.625 v1(43.375,63.3)
  Bottom Layer w0.12: v1(42.775,68.5) 43.53,67.745 43.53,66.812 43.14,66.422 43.14,63.585 43.375,63.35 v1(43.375,63.3)
PF13: CN10.34 U1.53 | length 29.2
  Top Layer w0.12: U1.53@45.975,70.25 46.9,70.25 47.785,71.135 48.315,71.135 v1(48.775,70.675)
  Signal Layer 2 w0.12: v1(48.775,64.1) 50.786,64.1 51.616,63.27 57.28,63.27 58.275,62.275 65.441,62.275 CN10.34@66.746,60.97
  Bottom Layer w0.12: v1(48.775,64.1) v1(48.775,70.675)
PF14: CN10.24 U1.54 | length 30.7
  Top Layer w0.12: v1@44.625,70.725 44.65,70.75 U1.54@45.975,70.75
  Signal Layer 2 w0.12: v1(43.875,75.275) 44.675,74.475 48.825,74.475 49.175,74.825 65.591,74.825 CN10.24@66.746,73.67
  Bottom Layer w0.12: v1(43.875,75.275) 45.437,73.713 45.437,71.562 v1(44.625,70.75)
PF15: CN7.4 U1.55 | length 66.1
  Top Layer w0.12: v1(43.15,77.175) 43.205,77.12 43.205,72.527 44.482,71.25 U1.55@45.975,71.25
  Signal Layer 2 w0.12: v1(8.35,77.35) 11.625,77.35 21.175,77.35 21.35,77.175 v1(43.15,77.175)
  Bottom Layer w0.12: CN7.4@5.786,99.07 7.56,97.296 7.56,90.482 7.875,90.167 7.875,79.65 8.875,78.65 8.875,77.85 8.7,77.675 v1@8.35,77.325
PG0: CN7.9 U1.56 | length 59.3
  Top Layer w0.12: v1(44.625,71.75) U1.56@45.975,71.75
  Signal Layer 2 w0.12: v1@8.375,75.775 9.325,74.825 12.075,74.825 12.55,75.3 18.769,75.3 19.664,74.405 23.194,74.405 24.099,75.31 40.251,75.31 43.051,72.51 43.34,72.51 44.1,71.75 v1(44.625,71.75)
  Bottom Layer w0.12: CN7.9@3.246,91.45 4.496,90.2 6.35,90.2 6.95,89.6 6.95,77.175 v1(8.375,75.75)
PG1: CN7.10 U1.57 | length 56.5
  Top Layer w0.12: v1(43.875,72.75) 44.375,72.25 U1.57@45.975,72.25
  Signal Layer 2 w0.12: v1(8.35,76.5) 9.775,75.075 11.986,75.075 12.451,75.54 18.274,75.54 18.869,75.54 19.764,74.645 23.02,74.645 23.025,74.65 23.1,74.65 24,75.55 40.35,75.55 43.15,72.75 v1(43.875,72.75)
  Bottom Layer w0.12: CN7.10@5.786,91.45 7.2,90.036 7.2,77.65 v1(8.35,76.5)
PG2: CN7.21 U1.87 | length 46.5
  Top Layer w0.12: v1(36.9,73.35) U1.87@36.9,81.825
  Signal Layer 2 w0.12: CN7.21@3.246,76.21 4.48,74.976 6.313,74.976 6.933,74.356 6.933,72.523 ; 6.932,72.525 7.841,71.615 16.265,71.615 17.8,73.15 25.05,73.15 26.025,74.125 28.111,74.125 28.886,73.35 v1(36.9,73.35)
PG3: CN12.12 U1.88 | length 103.8
  Top Layer w0.25: U1.88@36.4,81.825 36.425,81.85 36.425,82.875 v1(36.725,83.175)
  Signal Layer 2 w0.12: v1(24.075,37.8) 24.72,37.155 34.898,37.155 35.473,36.58 42.055,36.58 43.065,37.59 44.324,37.59 44.674,37.24 54.14,37.24 56.35,39.45 65.546,39.45 CN12.12@66.746,40.65 ; v1(25.375,81.625) 25.85,82.1 35.65,82.1 v1(36.725,83.175)
  Bottom Layer w0.12: v1(24.075,37.8) 24.075,45.393 23.375,46.093 23.375,47.375 23.83,47.83 23.83,53.88 24.12,54.17 24.12,57.712 23.825,58.007 23.825,73.725 25.375,75.275 v1(25.375,81.625)
PG4: CN7.26 SB38.2 U1.89 | length 109
  Top Layer w0.12: v1(35.5,72.2) 35.5,78.309 35.955,78.764 35.955,80.051 35.9,80.106 U1.89@35.9,81.825
  Top Layer w0.3: SB38.2@36.25,17.4 v1(36.25,18.475)
  Signal Layer 2 w0.12: CN7.26@5.786,71.13 17.88,71.13 17.958,71.209 v1@18.037,71.13 ; v1(18.075,71.125) 25.9,71.125 26.975,72.2 v1(35.5,72.2) ; v1(24,27.5) 24.5,27 26.421,27 26.706,26.715 32.31,26.715 v1(33.475,25.55)
  Bottom Layer w0.12: v1(18.075,71.125) 17.66,70.71 17.66,64.266 17.16,63.766 17.16,58.435 17.6,57.995 17.6,57.627 19.75,55.477 19.75,42.7 19.45,42.4 19.45,32.15 20.325,31.275 23.325,31.275 23.995,30.605 23.995,27.505 v1(24,27.5) ; v1(33.475,25.55) 36.96,22.065 36.96,19.185 v1(36.25,18.475)
PG5: CN19.18 SB36.1 U1.90 | length 68.9
  Top Layer w0.12: U1.90@35.4,81.825 35.4,80.325 35.5,80.225 v1(35.5,79.175) ; v1(56.5,46.475) 56.513,46.488 58.738,46.488 SB36.1@58.75,46.5
  Signal Layer 2 w0.12: v1(31.35,51.725) 33.43,49.645 46.07,49.645 46.675,50.25 49.406,50.25 53.181,46.475 54.025,46.475 ; v1(31.9,79.175) v1(35.5,79.175) ; 53.925,46.475 54.025,46.475 ; v1(56.5,46.475) 54.025,46.475
  Bottom Layer w0.12: v1(31.9,79.175) 31.9,67.446 30.42,65.966 30.42,63.795 28.945,62.32 28.945,61.58 29.84,60.685 29.84,57.353 30.135,57.058 30.135,53.979 31.105,53.009 31.105,52.01 31.35,51.765 v1(31.35,51.725) 32.15,50.925 CN19.18@32.15,49.35
PG6: CN5.9 CN10.5 U1.91 | length 40.8
  Top Layer w0.12: U1.91@34.9,81.825 34.9,83.042 38.375,86.517 38.375,87.143 43.132,91.9 45.294,91.9 45.969,92.575 v1(52.75,92.575)
  Signal Layer 2 w0.12: v1(53.025,98.075) 53.048,98.052 59.124,98.052 CN5.9@59.126,98.054 60.921,98.054 62.445,96.53 CN10.5@64.206,96.53
  Bottom Layer w0.12: v1(52.75,92.575) 52.75,94.35 53.025,94.625 v1(53.025,98.075)
PG7: CN12.18 CN14.12 SB13.2 TP67.1 U1.92 | length 157
  Top Layer w0.12: U1.92@34.4,81.825 34.4,83.056 34.789,83.445 34.963,83.445 35.5,83.982 v1(35.5,85.55)
  Top Layer w0.25: TP67.1@39.625,8.875 40.3,9.55 CN14.12@43.185,9.55
  Top Layer w0.3: v1(37.75,8.075) SB13.2@37.75,9.15 38.025,8.875 TP67.1@39.625,8.875
  Signal Layer 2 w0.12: v1(16.9,84.4) 18.795,86.295 26.644,86.295 27.409,85.53 35.48,85.53 v1(35.5,85.55) ; v1(25.4,27.5) 25.45,27.55 26.211,27.55 26.806,26.955 32.82,26.955 v1(33.405,26.37) 39.581,26.37 42.426,29.215 44.651,29.215 45.151,29.715 53.522,29.715 53.762,29.955 57.63,29.955 59.475,31.8 65.516,31.8 CN12.18@66.746,33.03
  Bottom Layer w0.12: v1(16.9,84.4) 20.385,80.915 20.385,77.235 19.215,76.065 19.215,68.01 20.19,67.035 20.19,60.8 22.455,58.534 22.455,46.334 23.37,45.419 23.37,33.284 24.475,32.179 24.475,28.425 v1(25.4,27.5) ; v1(33.405,26.37) 37.2,22.575 37.2,12.4 37.75,11.85 v1(37.75,8.075)
PG9: CN19.19 SB33.1 U1.124 | length 73.3
  Top Layer w0.12: U1.124@24.325,72.25 25.465,72.25 25.715,72.5 v1(25.75,72.5) ; v1(56.7,45) SB33.1@58.75,45
  Signal Layer 2 w0.12: v1(29.575,43.75) 30.142,43.75 32.552,41.341 32.552,40.491 34.762,38.28 36.777,38.28 37.272,37.785 40.33,37.785 40.935,38.39 47.751,38.39 48.826,39.465 50.076,39.465 55.611,45 v1(56.7,45)
  Bottom Layer w0.12: v1(25.75,72.5) 25.75,70.336 27.18,68.906 27.18,64.387 25.95,63.157 25.95,45.675 26.976,44.649 27.926,44.649 28.825,43.75 v1(29.575,43.75) 29.575,43.714 30.194,43.095 32.13,43.095 32.4,42.825 CN19.19@32.4,41.8
PG10: CN19.21 SB31.1 U1.125 | length 84.6
  Top Layer w0.12: U1.125@24.325,71.75 25.825,71.75 v1(26.6,72.525) ; v1(56.35,52.025) 56.975,51.4 58.623,51.4
  Signal Layer 2 w0.12: v1(29.1,44.425) 29.807,44.425 32.792,41.44 32.792,40.59 34.861,38.52 36.876,38.52 37.372,38.025 40.231,38.025 40.836,38.63 47.651,38.63 50.114,41.093 51.364,41.093 55.796,45.525 57.775,45.525 58.66,46.41 58.66,49.715 v1(56.35,52.025)
  Bottom Layer w0.12: v1(26.6,72.525) 26.19,72.115 26.19,70.235 27.42,69.005 27.42,64.288 26.2,63.068 26.2,46.175 v1(26.892,45.483) 27.486,44.889 28.636,44.889 v1(29.1,44.425) 29.807,44.425 30.897,43.335 32.59,43.335 32.9,43.025 CN19.21@32.9,41.8
PG11: CN19.16 SB34.1 U1.126 | length 60
  Top Layer w0.12: U1.126@24.325,71.25 25.775,71.25 26.541,72.016 27.759,72.016 28.175,71.6 v1(31.4,71.6) ; v1(53.075,48.675) 53.75,48 SB34.1@55.4,48
  Signal Layer 2 w0.12: v1(30.6,51.3) 30.895,51.595 30.895,51.913 31.182,52.2 31.95,52.2 34.265,49.885 45.971,49.885 46.576,50.49 49.505,50.49 50.523,49.473 51.248,48.748 51.32,48.675 v1(53.075,48.675)
  Bottom Layer w0.12: v1(31.4,71.6) 31.4,67.286 30.18,66.066 30.18,63.894 28.705,62.419 28.705,61.481 29.6,60.586 29.6,57.254 29.895,56.959 29.895,53.88 30.865,52.91 30.865,51.579 30.6,51.314 v1(30.6,51.3) 31.65,50.25 CN19.16@31.65,49.35
PG13: CN19.62 SB37.1 U1.128 | length 66.7
  Top Layer w0.12: U1.128@24.325,70.25 26.175,70.25 26.59,69.835 27.541,69.835 27.931,70.225 v1(40.3,70.225) ; v1(47.225,52.05) 52.9,52.05 54.75,53.9 v1(57.1,53.9) ; v1(57.5,43.5) SB37.1@58.75,43.5
  Bottom Layer w0.12: v1(40.3,70.225) 40.3,67.504 42.125,65.679 42.125,57.65 43.15,56.625 45.175,56.625 47.225,54.575 v1(47.225,52.05) 46.619,52.05 44.919,50.35 43.275,50.35 43.16,50.235 43.16,49.36 CN19.62@43.15,49.35 ; v1(57.1,53.9) 57.5,53.5 v1(57.5,43.5)
PG15: CN9.6 CN10.27 U1.132 | length 40.8
  Top Layer w0.12: U1.132@24.325,68.25 29.15,68.25 v1(30.375,69.475)
  Signal Layer 2 w0.12: v1(30.375,69.475) 42.35,69.475 42.85,68.975 48.625,68.975 49.01,68.59 CN9.6@59.126,68.59 CN10.27@64.206,68.59
PH0: CN7.29 SB3.2 | length 48
  Top Layer w0.12: v1(33.35,54.55) 34.07,54.55 SB3.2@34.244,54.377
  Signal Layer 2 w0.12: v1(1.425,52.98) 2.16,52.245 25.709,52.245 27.729,54.265 33.065,54.265 v1(33.35,54.55)
  Bottom Layer w0.12: v1(1.425,52.98) 1.425,64.229 CN7.29@3.246,66.05
PH1: CN7.31 SB4.2 | length 53.4
  Top Layer w0.12: SB4.2@39.256,54.314 39.775,53.795 v1(39.775,53.05)
  Signal Layer 2 w0.12: v1(1.914,51.637) 2.282,52.005 25.809,52.005 27.829,54.025 35.693,54.025 36.668,53.05 v1(39.775,53.05)
  Bottom Layer w0.12: v1(1.914,51.637) 1.88,51.671 1.88,53.169 1.665,53.384 1.665,61.929 CN7.31@3.246,63.51
RD_N: R86.1 U17.22 U18.6 U19.8 | length 27.2
  Top Layer w0.1: U17.22@37.075,32.225 37.075,32.025 ccw(c37.288,32.025) 37.137,31.874 cw(c36.987,31.723) 37.2,31.723 37.2,30.249 ccw(c38.224,30.249) 37.5,29.525 cw(c37.259,29.284) 37.6,29.284 37.6,29.113 cw(c36.665,29.113) 37.326,28.452 cw(c37.2,28.578) v1(37.2,28.4) cw(c37.2,28.228) 37.322,28.349 37.571,28.101 cw(c37.5,28.03) 37.6,28.03 cw(c37.5,28.03) 37.571,27.959 cw(c37.5,28.03) 37.5,27.93 37.473,27.93 ccw(c37.473,27.765) 37.357,27.882 R86.1@37.2,27.725 ; U19.8@42.88,27.2 cw(c44.763,27.2) 43.432,28.532 43.606,28.706 cw(c44.075,28.236) 44.075,28.9 44.912,28.9 ccw(c44.912,29.63) 45.428,29.114 ccw(c44.529,30.012) 45.8,30.012 45.8,30.4 cw(c47.07,30.4) 46.172,31.298 46.204,31.33 ccw(c45.972,31.562) 46.3,31.562 U18.6@46.3,32.2 46.3,32.715 ccw(c45.19,32.715) v1(45.975,33.5)
  Bottom Layer w0.1: v1(37.2,28.4) ccw(c36.234,29.366) 37.6,29.366 37.6,29.412 cw(c39.813,29.412) 38.248,30.977 38.846,31.574 cw(c40.175,30.245) 40.175,32.125 40.395,32.125 cw(c40.395,30.595) 41.477,31.677 41.56,31.594 ccw(c43.356,33.39) 43.356,30.85 44.559,30.85 ccw(c44.559,32.216) 45.525,31.25 45.806,31.531 ccw(c44.734,32.604) 46.251,32.604 46.251,33.043 ccw(c45.793,33.043) 46.117,33.366 45.983,33.5 v1(45.975,33.5)
RD_P: R87.1 U17.23 U18.1 U19.6 | length 25.6
  Top Layer w0.1: U17.23@37.575,32.225 37.575,32.025 cw(c37.362,32.025) 37.512,31.874 ccw(c37.663,31.723) 37.45,31.723 37.45,30.249 ccw(c38.224,30.249) 37.677,29.702 cw(c37.259,29.284) 37.85,29.284 37.85,29.113 ccw(c38.785,29.113) 38.124,28.452 ccw(c38.25,28.578) v1(38.25,28.4) ccw(c38.25,28.228) 38.128,28.349 37.879,28.101 ccw(c37.95,28.03) 37.85,28.03 ccw(c37.95,28.03) 37.879,27.959 ccw(c37.95,28.03) 37.95,27.93 37.977,27.93 cw(c37.977,27.765) 38.093,27.882 R87.1@38.25,27.725 ; U19.6@45.42,27.2 45.42,28.069 cw(c46.991,28.069) 45.88,29.18 46.088,29.388 ccw(c45.576,29.9) U18.1@46.3,29.9 46.3,30.723 cw(c47.005,30.723) 46.506,31.222 46.732,31.447 ccw(c46.28,31.651) 46.776,31.651 v1(46.776,33.516)
  Bottom Layer w0.1: v1(38.25,28.4) cw(c39.216,29.366) 37.85,29.366 37.85,29.412 cw(c39.813,29.412) 38.425,30.8 39.023,31.398 cw(c40.175,30.245) 40.175,31.875 40.395,31.875 cw(c40.395,30.595) 41.3,31.5 41.383,31.417 ccw(c43.356,33.39) 43.356,30.6 44.559,30.6 ccw(c44.559,32.216) 45.702,31.073 46.02,31.391 ccw(c44.859,32.552) 46.501,32.552 46.501,33.037 cw(c46.971,33.037) 46.638,33.37 46.776,33.508 v1(46.776,33.516)
RESET_MCU: B2.3 B2.4 C73.2 SB46.1 U1.25 U14.1 | length 88.9
  Top Layer w0.12: SB46.1@15.128,85.575 15.153,85.551 15.238,85.551 15.262,85.575 15.425,85.575 v1(16.1,86.25) ; v1(37.925,102.85) U14.1@37.925,102.144 B2.3@40.444,102.144 ; v1(38.4,61.45) U1.25@38.4,60.175 38.4,59.175 38.6,58.975 C73.2@38.6,58.05 ; B2.3@40.45,102.15 B2.4@46.05,102.15
  Signal Layer 2 w0.12: v1(16.1,86.25) 16.8,86.95 32.809,86.95 33.509,86.25 34.003,86.25 40.783,86.25 v1(42.925,88.392)
  Bottom Layer w0.12: v1(37.925,102.85) 40.259,102.85 41.65,101.459 41.65,89.667 v1(42.925,88.392) 42.925,80.15 38.038,75.263 38.038,61.812 v1(38.4,61.45)
RMII.CRS_DV: R71.1 U1.115 | length 62.8
  Top Layer w0.12: v1(18.975,76.875) 19.536,76.875 19.576,76.915 22.786,76.915 22.951,76.75 U1.115@24.325,76.75 ; v1(21.975,36.45) 28.726,36.45 31.853,39.577 31.853,39.863 32.52,40.53 34.52,40.53 35.025,40.025 R71.1@35.025,39.4
  Bottom Layer w0.12: v1(18.975,76.875) 18.975,59.275 21.975,56.275 v1(21.975,36.45)
RMII.MDC: U1.27 U17.13 | length 58
  Top Layer w0.12: v1(33.85,35.4) 33.863,35.412 34.863,35.412 U17.13@34.875,35.425 ; U1.27@39.4,60.175 39.4,62.125 39.683,62.408 44.388,62.408 45.075,61.72 47.141,61.72 47.451,61.41 50.09,61.41 v1(51.25,60.25)
  Signal Layer 2 w0.12: v1(33.85,35.4) 34.31,35.86 41.747,35.86 42.187,35.42 42.607,35.42 42.843,35.655 45.33,35.655 46.435,36.76 50.19,36.76 v1(50.5,36.45)
  Bottom Layer w0.12: v1(50.5,36.45) 50.5,39.55 51.6,40.65 51.6,45.275 51.25,45.625 v1(51.25,60.25)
